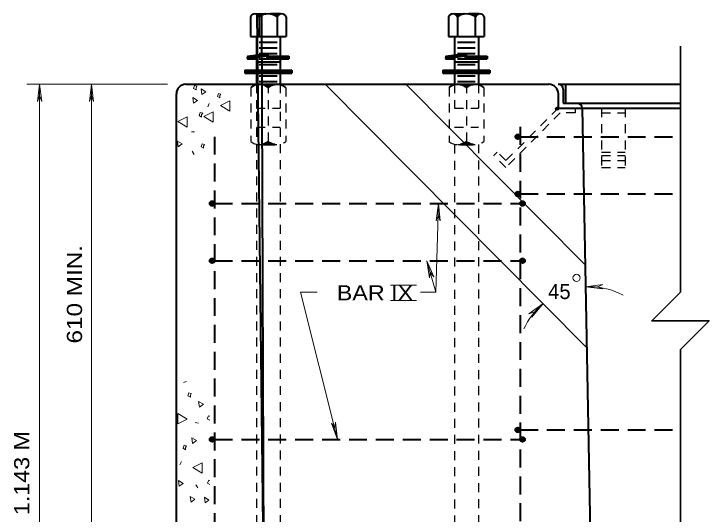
# Model space of a CAD drawing. Extents: x 312583 to 312854, y 144419 to 144597.
# Drawn here: x 312746.73 to 312781.61, y 144471.31 to 144496.43 of the extents above; entities that cross this region are included whole.
import ezdxf

# ---------------------------------------------------------------- set-up
doc = ezdxf.new("R2010")
doc.units = 0
doc.header["$LTSCALE"] = 0.3
doc.header["$PDMODE"] = 32
doc.header["$PDSIZE"] = 0.15
doc.linetypes.add('MEDIUM_DASHED', pattern=[4.5, 3, -1.5])
doc.linetypes.add('SHORT_DASHED', pattern=[2.7, 1.5, -1.2])
doc.layers.add('1', color=7, linetype='Continuous', lineweight=25)
doc.layers.add('2', color=7, linetype='Continuous', lineweight=13)

msp = doc.modelspace()

# ---------------------------------------------------------------- linework, layer by layer
at = {"layer": '1', "lineweight": 40}
for p, q in [((312758.5997, 144496.2928), (312758.5997, 144495.3038)), ((312759.0443, 144496.2928), (312759.0443, 144495.3038)), ((312759.9413, 144496.2928), (312759.9413, 144495.3038)), ((312760.3937, 144496.2928), (312760.3937, 144495.3038)), ((312768.5433, 144496.2928), (312768.5433, 144495.3038)), ((312768.988, 144496.2928), (312768.988, 144495.3038)), ((312769.885, 144496.2928), (312769.885, 144495.3038)), ((312770.3373, 144496.2928), (312770.3373, 144495.3038)), ((312758.5997, 144495.3038), (312760.3937, 144495.3038)), ((312758.8987, 144495.3038), (312758.8987, 144492.9041)), ((312759.0443, 144495.0201), (312759.9413, 144495.0201)), ((312760.0947, 144495.3038), (312760.0947, 144492.9041)), ((312768.5433, 144495.3038), (312770.3373, 144495.3038)), ((312768.8423, 144495.3038), (312768.8423, 144492.9041)), ((312768.988, 144495.0201), (312769.885, 144495.0201)), ((312770.0383, 144495.3038), (312770.0383, 144492.9041)), ((312759.0443, 144494.7364), (312759.9413, 144494.7364)), ((312768.988, 144494.7364), (312769.885, 144494.7364)), ((312758.454, 144494.3148), (312758.454, 144494.1768)), ((312759.0443, 144494.4528), (312759.9413, 144494.4528)), ((312759.4507, 144494.3148), (312760.5317, 144494.3148)), ((312760.5317, 144494.3148), (312760.5317, 144494.1768)), ((312768.3977, 144494.3148), (312768.3977, 144494.1768)), ((312768.988, 144494.4528), (312769.885, 144494.4528)), ((312769.3943, 144494.3148), (312770.4753, 144494.3148)), ((312770.4753, 144494.3148), (312770.4753, 144494.1768)), ((312758.8987, 144494.0311), (312760.0947, 144494.0311)), ((312759.0443, 144494.1768), (312759.9413, 144494.1768)), ((312759.4123, 144494.1768), (312760.5317, 144494.1768)), ((312768.8423, 144494.0311), (312770.0383, 144494.0311)), ((312768.988, 144494.1768), (312769.885, 144494.1768)), ((312769.356, 144494.1768), (312770.4753, 144494.1768)), ((312758.316, 144493.6094), (312760.6773, 144493.6094)), ((312758.316, 144493.6094), (312758.316, 144493.4638)), ((312759.0443, 144493.8931), (312759.9413, 144493.8931)), ((312760.6773, 144493.6094), (312760.6773, 144493.4638)), ((312768.2597, 144493.6094), (312770.621, 144493.6094)), ((312768.2597, 144493.6094), (312768.2597, 144493.4638)), ((312768.988, 144493.8931), (312769.885, 144493.8931)), ((312770.621, 144493.6094), (312770.621, 144493.4638)), ((312758.316, 144493.5711), (312760.6773, 144493.5711)), ((312758.316, 144493.5328), (312760.6773, 144493.5328)), ((312758.316, 144493.5021), (312760.6773, 144493.5021)), ((312758.316, 144493.4638), (312760.6773, 144493.4638)), ((312759.0443, 144493.3258), (312759.9413, 144493.3258)), ((312768.2597, 144493.5711), (312770.621, 144493.5711)), ((312768.2597, 144493.5328), (312770.621, 144493.5328)), ((312768.2597, 144493.5021), (312770.621, 144493.5021)), ((312768.2597, 144493.4638), (312770.621, 144493.4638)), ((312768.988, 144493.3258), (312769.885, 144493.3258)), ((312755.3643, 144492.9041), (312773.5727, 144492.9041)), ((312758.8987, 144492.9041), (312760.0947, 144492.9041)), ((312759.0443, 144493.0421), (312759.9413, 144493.0421)), ((312759.0597, 144492.9041), (312759.9337, 144492.9041)), ((312768.8423, 144492.9041), (312770.0383, 144492.9041)), ((312768.988, 144493.0421), (312769.885, 144493.0421)), ((312769.0033, 144492.9041), (312769.8773, 144492.9041)), ((312774.048, 144492.9041), (312780.1813, 144492.9041)), ((312774.4083, 144492.9041), (312774.4083, 144491.9458)), ((312774.2933, 144492.6588), (312774.2933, 144491.9458)), ((312754.8813, 144492.4211), (312754.8813, 144449.7791)), ((312774.048, 144492.4211), (312774.048, 144491.7004)), ((312774.2933, 144491.9458), (312780.1813, 144491.9458)), ((312774.048, 144491.7004), (312780.1813, 144491.7004)), ((312775.2517, 144491.7004), (312775.9647, 144453.6124))]:
    msp.add_line(p, q, dxfattribs=at)
at = {"layer": '1', "linetype": 'SHORT_DASHED'}
for p, q in [((312758.8987, 144492.9041), (312758.8987, 144491.6928)), ((312759.4967, 144492.9041), (312759.4967, 144489.8681)), ((312760.0947, 144492.9041), (312760.0947, 144491.6928)), ((312768.8423, 144492.9041), (312768.8423, 144491.6928)), ((312769.4403, 144492.9041), (312769.4403, 144489.8681)), ((312770.0383, 144492.9041), (312770.0383, 144491.6928)), ((312758.6227, 144492.7431), (312758.6227, 144490.0291)), ((312760.3707, 144492.7431), (312760.3707, 144490.0291)), ((312768.5663, 144492.7431), (312768.5663, 144490.0291)), ((312770.3143, 144492.7431), (312770.3143, 144490.0291)), ((312758.8987, 144491.6928), (312760.0947, 144491.6928)), ((312758.8987, 144491.5164), (312758.8987, 144458.2738)), ((312760.0947, 144491.5164), (312760.0947, 144458.2738)), ((312768.8423, 144491.6928), (312770.0383, 144491.6928)), ((312774.048, 144491.7004), (312771.4183, 144489.0708)), ((312774.8913, 144491.7004), (312774.8913, 144491.4628)), ((312776.21, 144491.7004), (312776.21, 144488.7258)), ((312777.406, 144491.7004), (312777.406, 144488.7258)), ((312774.1477, 144491.4628), (312771.4183, 144488.7258)), ((312774.8913, 144491.4628), (312774.1477, 144491.4628)), ((312776.21, 144491.4628), (312777.406, 144491.4628)), ((312758.8987, 144490.7421), (312760.0947, 144490.7421)), ((312768.8423, 144490.7421), (312770.0383, 144490.7421)), ((312759.0597, 144489.8681), (312759.9337, 144489.8681)), ((312768.8423, 144489.8681), (312768.8423, 144458.2738)), ((312769.0033, 144489.8681), (312769.8773, 144489.8681)), ((312770.0383, 144489.8834), (312770.0383, 144458.2738)), ((312770.989, 144489.4924), (312770.8203, 144489.3238)), ((312771.4183, 144489.0708), (312770.989, 144489.4924)), ((312776.21, 144489.4924), (312777.406, 144489.4924)), ((312771.4183, 144488.7258), (312770.8203, 144489.3238)), ((312776.21, 144489.3238), (312777.406, 144489.3238)), ((312776.21, 144489.0708), (312777.406, 144489.0708)), ((312776.21, 144488.7258), (312777.406, 144488.7258))]:
    msp.add_line(p, q, dxfattribs=at)
at = {"layer": '1', "lineweight": 35}
for p, q in [((312775.474, 144479.6714), (312762.3487, 144492.9041)), ((312775.3973, 144483.8344), (312766.3967, 144492.9041))]:
    msp.add_line(p, q, dxfattribs=at)
at = {"layer": '1', "lineweight": 13}
for p, q in [((312754.9043, 144491.3324), (312754.9043, 144491.8538)), ((312756.5373, 144491.9304), (312756.4607, 144491.7618)), ((312754.8813, 144491.3478), (312754.9043, 144491.3324)), ((312755.6403, 144490.5121), (312755.7937, 144490.5198)), ((312755.6787, 144489.5384), (312755.7707, 144489.3698)), ((312754.9043, 144488.9788), (312754.8813, 144488.9634)), ((312755.2417, 144477.9311), (312755.3873, 144477.9694)), ((312755.8243, 144475.9148), (312755.993, 144475.8764)), ((312755.142, 144473.9598), (312755.0653, 144473.7911)), ((312755.855, 144472.7791), (312755.9547, 144472.6334))]:
    msp.add_line(p, q, dxfattribs=at)
at = {"layer": '1', "linetype": 'MEDIUM_DASHED', "lineweight": 40}
for p, q in [((312772.1313, 144490.7574), (312772.1313, 144451.0748)), ((312756.798, 144490.2668), (312756.798, 144450.5994)), ((312772.1313, 144490.2668), (312780.1813, 144490.2668)), ((312772.1313, 144487.3918), (312780.1813, 144487.3918)), ((312756.798, 144486.9088), (312772.1313, 144486.9088)), ((312756.798, 144484.0338), (312772.1313, 144484.0338)), ((312772.1313, 144475.5468), (312780.1813, 144475.5468)), ((312756.798, 144475.0638), (312772.1313, 144475.0638))]:
    msp.add_line(p, q, dxfattribs=at)
at = {"layer": '1', "lineweight": 40}
for points in [[(312758.8757, 144496.4308), (312759.3817, 144496.4308), (312759.2973, 144496.4154), (312759.236, 144496.4001), (312759.144, 144496.3694), (312759.052, 144496.3004), (312759.0137, 144496.3618), (312758.9753, 144496.3924), (312758.8987, 144496.4308), (312759.3433, 144496.4308), (312759.213, 144496.4001), (312759.121, 144496.3618), (312759.052, 144496.3158), (312758.983, 144496.3848), (312758.9293, 144496.4231), (312759.2897, 144465.0204), (312759.167, 144496.3848), (312759.052, 144496.3234), (312758.9523, 144496.4154), (312759.2437, 144496.4154), (312759.052, 144496.3388), (312758.9753, 144496.4078), (312759.213, 144496.4154), (312759.0443, 144496.3464), (312758.9907, 144496.4001), (312759.1747, 144496.4078), (312759.052, 144496.3618), (312759.0137, 144496.3924), (312759.1287, 144496.4001), (312759.0597, 144496.3694), (312759.0367, 144496.3924), (312759.0903, 144496.3924), (312759.052, 144496.3848)], [(312760.11, 144496.4308), (312759.6117, 144496.4308), (312759.696, 144496.4154), (312759.7497, 144496.4001), (312759.8493, 144496.3694), (312759.9413, 144496.3004), (312759.972, 144496.3618), (312760.018, 144496.3924), (312760.0947, 144496.4308), (312759.65, 144496.4308), (312759.7803, 144496.4001), (312759.8647, 144496.3618), (312759.9337, 144496.3158), (312760.0103, 144496.3848), (312760.064, 144496.4231), (312759.7037, 144496.4231), (312759.8263, 144496.3848), (312759.9337, 144496.3234), (312760.0333, 144496.4154), (312759.7497, 144496.4154), (312759.9413, 144496.3388), (312760.018, 144496.4078), (312759.7803, 144496.4154), (312759.949, 144496.3464), (312760.0027, 144496.4001), (312759.811, 144496.4078), (312759.9413, 144496.3618), (312759.9797, 144496.3924), (312759.8647, 144496.4001), (312759.9337, 144496.3694), (312759.9567, 144496.3924), (312759.903, 144496.3924), (312759.9413, 144496.3848)], [(312768.8193, 144496.4308), (312769.3253, 144496.4308), (312769.241, 144496.4154), (312769.1797, 144496.4001), (312769.0877, 144496.3694), (312768.9957, 144496.3004), (312768.9573, 144496.3618), (312768.919, 144496.3924), (312768.8423, 144496.4308), (312769.287, 144496.4308), (312769.1567, 144496.4001), (312769.0647, 144496.3618), (312768.9957, 144496.3158), (312768.9267, 144496.3848), (312768.873, 144496.4231), (312769.2333, 144496.4231), (312769.1107, 144496.3848), (312768.9957, 144496.3234), (312768.896, 144496.4154), (312769.1873, 144496.4154), (312768.9957, 144496.3388), (312768.919, 144496.4078), (312769.1567, 144496.4154), (312768.988, 144496.3464), (312768.9343, 144496.4001), (312769.1183, 144496.4078), (312768.9957, 144496.3618), (312768.9573, 144496.3924), (312769.0723, 144496.4001), (312769.0033, 144496.3694), (312768.9803, 144496.3924), (312769.034, 144496.3924), (312768.9957, 144496.3848)], [(312770.0537, 144496.4308), (312769.5553, 144496.4308), (312769.6397, 144496.4154), (312769.6933, 144496.4001), (312769.793, 144496.3694), (312769.885, 144496.3004), (312769.9157, 144496.3618), (312769.9617, 144496.3924), (312770.0383, 144496.4308), (312769.5937, 144496.4308), (312769.724, 144496.4001), (312769.8083, 144496.3618), (312769.8773, 144496.3158), (312769.954, 144496.3848), (312770.0077, 144496.4231), (312769.6473, 144496.4231), (312769.77, 144496.3848), (312769.8773, 144496.3234), (312769.977, 144496.4154), (312769.6933, 144496.4154), (312769.885, 144496.3388), (312769.9617, 144496.4078), (312769.724, 144496.4154), (312769.8927, 144496.3464), (312769.9463, 144496.4001), (312769.7547, 144496.4078), (312769.885, 144496.3618), (312769.9233, 144496.3924), (312769.8083, 144496.4001), (312769.8773, 144496.3694), (312769.9003, 144496.3924), (312769.8467, 144496.3924), (312769.885, 144496.3848)], [(312758.454, 144494.3148), (312759.4967, 144494.4528), (312759.4123, 144494.1768)], [(312759.4507, 144494.3148), (312758.454, 144494.1768), (312758.8987, 144494.1768)], [(312758.8987, 144494.1768), (312758.4617, 144494.1921), (312758.477, 144494.3071), (312759.466, 144494.4374), (312759.4353, 144494.3301), (312758.891, 144494.2534), (312758.8833, 144494.1921), (312758.4847, 144494.2074), (312758.4923, 144494.2841), (312759.443, 144494.4144), (312759.42, 144494.3378), (312758.868, 144494.2534), (312758.8603, 144494.2074), (312758.5, 144494.2228), (312758.5, 144494.2611), (312759.4047, 144494.3914), (312759.4047, 144494.3684), (312758.8757, 144494.2688), (312758.8373, 144494.2534), (312758.7223, 144494.2304), (312758.523, 144494.2381), (312759.3817, 144494.3761), (312758.6533, 144494.2381)], [(312759.4353, 144494.1921), (312760.5163, 144494.1921), (312760.5163, 144494.2994), (312759.4737, 144494.2918), (312759.4353, 144494.2074), (312760.501, 144494.2074), (312760.4933, 144494.2841), (312759.4813, 144494.2764), (312759.4583, 144494.2228), (312760.478, 144494.2304), (312760.4627, 144494.2534), (312760.455, 144494.2688), (312759.489, 144494.2611), (312759.4737, 144494.2381), (312760.455, 144494.2458)], [(312768.3977, 144494.3148), (312769.4403, 144494.4528), (312769.356, 144494.1768)], [(312769.3943, 144494.3148), (312768.3977, 144494.1768), (312768.8423, 144494.1768)], [(312768.8423, 144494.1768), (312768.4053, 144494.1921), (312768.4207, 144494.3071), (312769.4097, 144494.4374), (312769.379, 144494.3301), (312768.8347, 144494.2534), (312768.827, 144494.1921), (312768.4283, 144494.2074), (312768.436, 144494.2841), (312769.3867, 144494.4144), (312769.3637, 144494.3378), (312768.8117, 144494.2534), (312768.804, 144494.2074), (312768.4437, 144494.2228), (312768.4437, 144494.2611), (312769.3483, 144494.3914), (312769.3483, 144494.3684), (312768.8193, 144494.2688), (312768.781, 144494.2534), (312768.666, 144494.2304), (312768.4667, 144494.2381), (312769.3253, 144494.3761), (312768.597, 144494.2381)], [(312769.379, 144494.1921), (312770.46, 144494.1921), (312770.46, 144494.2994), (312769.4173, 144494.2918), (312769.379, 144494.2074), (312770.4447, 144494.2074), (312770.437, 144494.2841), (312769.425, 144494.2764), (312769.402, 144494.2228), (312770.4217, 144494.2304), (312770.4063, 144494.2534), (312770.3987, 144494.2688), (312769.4327, 144494.2611), (312769.4173, 144494.2381), (312770.3987, 144494.2458)], [(312759.1747, 144492.8964), (312759.8263, 144492.8964), (312759.7497, 144492.8811), (312759.6807, 144492.8581), (312759.6117, 144492.8351), (312759.5657, 144492.8044), (312759.5043, 144492.7661), (312759.4967, 144492.7584), (312759.374, 144492.8351), (312759.2667, 144492.8734), (312759.2053, 144492.8888), (312759.7803, 144492.8964), (312759.7343, 144492.8888), (312759.6807, 144492.8734), (312759.6117, 144492.8504), (312759.535, 144492.8121), (312759.5197, 144492.7891), (312759.4967, 144492.7661), (312759.3893, 144492.8428), (312759.2667, 144492.8811), (312759.696, 144492.8888), (312759.5887, 144492.8504), (312759.4967, 144492.7891), (312759.3127, 144492.8811), (312759.65, 144492.8811), (312759.4967, 144492.7814), (312759.351, 144492.8734), (312759.6193, 144492.8734), (312759.5043, 144492.8121), (312759.4047, 144492.8581), (312759.5733, 144492.8658), (312759.4967, 144492.8351), (312759.397, 144492.8504), (312759.4583, 144492.8198), (312759.4737, 144492.8581), (312759.489, 144492.7968), (312759.5273, 144492.8428), (312759.558, 144492.8428), (312759.5887, 144492.8581)], [(312769.1183, 144492.8964), (312769.77, 144492.8964), (312769.6933, 144492.8811), (312769.6243, 144492.8581), (312769.5553, 144492.8351), (312769.5093, 144492.8044), (312769.448, 144492.7661), (312769.4403, 144492.7584), (312769.3177, 144492.8351), (312769.2103, 144492.8734), (312769.149, 144492.8888), (312769.724, 144492.8964), (312769.678, 144492.8888), (312769.6243, 144492.8734), (312769.5553, 144492.8504), (312769.4787, 144492.8121), (312769.4633, 144492.7891), (312769.4403, 144492.7661), (312769.333, 144492.8428), (312769.2103, 144492.8811), (312769.6397, 144492.8888), (312769.5323, 144492.8504), (312769.4403, 144492.7891), (312769.2563, 144492.8811), (312769.5937, 144492.8811), (312769.4403, 144492.7814), (312769.2947, 144492.8734), (312769.563, 144492.8734), (312769.448, 144492.8121), (312769.3483, 144492.8581), (312769.517, 144492.8658), (312769.4403, 144492.8351), (312769.3407, 144492.8504), (312769.402, 144492.8198), (312769.4173, 144492.8581), (312769.4327, 144492.7968), (312769.471, 144492.8428), (312769.5017, 144492.8428), (312769.5323, 144492.8581)], [(312759.1747, 144489.8758), (312759.8263, 144489.8681), (312759.7497, 144489.8834), (312759.6807, 144489.9064), (312759.6117, 144489.9371), (312759.5657, 144489.9601), (312759.5043, 144490.0061), (312759.4967, 144490.0138), (312759.374, 144489.9371), (312759.2667, 144489.8911), (312759.2053, 144489.8758), (312759.7803, 144489.8758), (312759.7343, 144489.8834), (312759.6807, 144489.8911), (312759.6117, 144489.9218), (312759.535, 144489.9601), (312759.5197, 144489.9754), (312759.4967, 144489.9984), (312759.3893, 144489.9294), (312759.2667, 144489.8834), (312759.696, 144489.8834), (312759.5887, 144489.9218), (312759.4967, 144489.9754), (312759.3127, 144489.8911), (312759.65, 144489.8834), (312759.4967, 144489.9908), (312759.351, 144489.8988), (312759.6193, 144489.8911), (312759.5043, 144489.9601), (312759.4047, 144489.9064), (312759.5733, 144489.9064), (312759.4967, 144489.9294), (312759.397, 144489.9141), (312759.4583, 144489.9524), (312759.4737, 144489.9141), (312759.489, 144489.9678), (312759.5273, 144489.9218), (312759.558, 144489.9218), (312759.5887, 144489.9141)], [(312769.1183, 144489.8758), (312769.77, 144489.8681), (312769.6933, 144489.8834), (312769.6243, 144489.9064), (312769.5553, 144489.9371), (312769.5093, 144489.9601), (312769.448, 144490.0061), (312769.4403, 144490.0138), (312769.3177, 144489.9371), (312769.2103, 144489.8911), (312769.149, 144489.8758), (312769.724, 144489.8758), (312769.678, 144489.8834), (312769.6243, 144489.8911), (312769.5553, 144489.9218), (312769.4787, 144489.9601), (312769.4633, 144489.9754), (312769.4403, 144489.9984), (312769.333, 144489.9294), (312769.2103, 144489.8834), (312769.6397, 144489.8834), (312769.5323, 144489.9218), (312769.4403, 144489.9754), (312769.2563, 144489.8911), (312769.5937, 144489.8834), (312769.4403, 144489.9908), (312769.2947, 144489.8988), (312769.563, 144489.8911), (312769.448, 144489.9601), (312769.3483, 144489.9064), (312769.517, 144489.9064), (312769.4403, 144489.9294), (312769.3407, 144489.9141), (312769.402, 144489.9524), (312769.4173, 144489.9141), (312769.4327, 144489.9678), (312769.471, 144489.9218), (312769.5017, 144489.9218), (312769.5323, 144489.9141)]]:
    msp.add_lwpolyline(points, dxfattribs=at)
at = {"layer": '1', "lineweight": 35}
msp.add_lwpolyline([(312780.1813, 144494.8208), (312780.1813, 144482.4621), (312778.74, 144481.0284), (312781.615, 144481.0284), (312780.1813, 144479.5871), (312780.1813, 144468.2021), (312778.74, 144466.7608), (312781.615, 144466.7608), (312780.1813, 144465.3271), (312780.1813, 144447.8624)], dxfattribs=at)
at = {"layer": '1', "lineweight": 13}
for points in [[(312755.8703, 144492.7278), (312755.9163, 144492.8121), (312755.8013, 144492.8428), (312755.74, 144492.6894), (312755.8703, 144492.6204)], [(312756.1617, 144492.3828), (312756.361, 144492.5284), (312756.1233, 144492.6664)], [(312755.7477, 144491.9458), (312755.947, 144492.0914), (312755.7093, 144492.2294)], [(312757.074, 144492.3291), (312757.12, 144492.4058), (312757.005, 144492.4441), (312756.9513, 144492.2908), (312757.074, 144492.2218)], [(312757.5647, 144491.5471), (312757.5647, 144492.0608), (312757.097, 144491.8308)], [(312756.7367, 144490.9951), (312756.7367, 144491.5164), (312756.269, 144491.2788)], [(312755.4257, 144490.7421), (312755.4257, 144491.2634), (312754.958, 144491.0258)], [(312756.154, 144491.3631), (312756.2077, 144491.4474), (312756.085, 144491.4781), (312756.0313, 144491.3248), (312756.154, 144491.2558)], [(312754.981, 144489.7608), (312755.1727, 144489.9064), (312754.9427, 144490.0444)], [(312756.246, 144489.7991), (312756.292, 144489.8834), (312756.177, 144489.9141), (312756.1233, 144489.7608), (312756.246, 144489.6918)], [(312755.5867, 144477.2948), (312755.6327, 144477.3791), (312755.5177, 144477.4098), (312755.4563, 144477.2564), (312755.5867, 144477.1874)], [(312756.0467, 144476.6891), (312756.2383, 144476.8348), (312756.0007, 144476.9728)], [(312754.958, 144476.3671), (312754.958, 144475.8534), (312755.4257, 144476.0834)], [(312755.7017, 144474.8644), (312755.901, 144475.0101), (312755.6633, 144475.1481)], [(312755.349, 144474.6574), (312755.395, 144474.7418), (312755.28, 144474.7724), (312755.2187, 144474.6268), (312755.349, 144474.5501)], [(312756.1847, 144473.3694), (312756.1847, 144473.8908), (312755.717, 144473.6531)], [(312755.027, 144472.7101), (312755.2187, 144472.8558), (312754.9887, 144473.0014)], [(312755.625, 144471.9204), (312755.8167, 144472.0661), (312755.579, 144472.2041)], [(312756.3303, 144471.8744), (312756.522, 144472.0201), (312756.292, 144472.1658)]]:
    msp.add_lwpolyline(points, close=True, dxfattribs=at)
for points in [[(312756.5603, 144476.2368), (312756.499, 144476.2521), (312756.4377, 144476.0988), (312756.5603, 144476.0374)], [(312756.5603, 144473.0091), (312756.5067, 144473.0244), (312756.4453, 144472.8711), (312756.5603, 144472.8098)], [(312754.8737, 144471.8514), (312754.9043, 144471.9128), (312754.8737, 144471.9204)]]:
    msp.add_lwpolyline(points, dxfattribs=at)
at = {"layer": '1', "lineweight": 40}
for centre, radius in [((312772.0144, 144490.2658), 0.1198), ((312772.0144, 144490.2658), 0.0838), ((312772.0144, 144490.2658), 0.0587), ((312772.0144, 144487.3908), 0.1198), ((312772.0144, 144487.3908), 0.0838), ((312772.0144, 144487.3908), 0.0587), ((312756.6811, 144486.9116), 0.1198), ((312756.6811, 144486.9116), 0.0838), ((312756.6811, 144486.9116), 0.0587), ((312772.254, 144486.9116), 0.1198), ((312772.254, 144486.9116), 0.0838), ((312772.254, 144486.9116), 0.0587), ((312756.6811, 144484.0366), 0.1198), ((312756.6811, 144484.0366), 0.0838), ((312756.6811, 144484.0366), 0.0587), ((312772.254, 144484.0366), 0.1198), ((312772.254, 144484.0366), 0.0838), ((312772.254, 144484.0366), 0.0587), ((312772.0144, 144475.5449), 0.1198), ((312772.0144, 144475.5449), 0.0838), ((312772.0144, 144475.5449), 0.0587), ((312756.6811, 144475.0657), 0.1198), ((312756.6811, 144475.0657), 0.0838), ((312756.6811, 144475.0657), 0.0587), ((312772.254, 144475.0657), 0.1198), ((312772.254, 144475.0657), 0.0838), ((312772.254, 144475.0657), 0.0587)]:
    msp.add_circle(centre, radius, dxfattribs=at)
for centre, radius, start, end in [((312758.8223, 144496.186), 0.2489, 25.60064, 154.39936), ((312759.4957, 144495.6513), 0.7836, 55.04559, 124.95441), ((312760.1691, 144496.186), 0.2489, 25.60064, 154.39936), ((312768.766, 144496.186), 0.2489, 25.60064, 154.39936), ((312769.4394, 144495.6513), 0.7836, 55.04559, 124.95441), ((312770.1128, 144496.186), 0.2489, 25.60064, 154.39936), ((312759.0575, 144492.2191), 0.6817, 50.00693, 129.99306), ((312759.9338, 144492.2191), 0.6817, 50.00694, 129.99307), ((312769.0012, 144492.2191), 0.6817, 50.00693, 129.99306), ((312769.8775, 144492.2191), 0.6817, 50.00694, 129.99307), ((312774.0509, 144492.6616), 0.2396, 0, 90), ((312775.0092, 144491.7033), 0.2396, 0, 90)]:
    msp.add_arc(centre, radius, start, end, dxfattribs=at)
at = {"layer": '1', "linetype": 'SHORT_DASHED'}
for centre, start, end in [((312759.0575, 144490.5485), 230.00694, 309.99307), ((312759.9338, 144490.5485), 230.00693, 309.99306), ((312769.0012, 144490.5485), 230.00694, 309.99307), ((312769.8775, 144490.5485), 230.00693, 309.99306)]:
    msp.add_arc(centre, 0.6817, start, end, dxfattribs=at)
at = {"layer": '1'}
msp.add_point((312773.979, 144491.6698), dxfattribs=at)
at = {"layer": '2'}
for p, q in [((312754.4443, 144492.9041), (312747.3757, 144492.9041)), ((312748.0197, 144492.9041), (312747.9123, 144492.0378)), ((312748.0197, 144492.9041), (312748.127, 144492.0378)), ((312748.0197, 144449.7791), (312748.0197, 144492.9041)), ((312750.6263, 144492.9041), (312750.519, 144492.0378)), ((312750.6263, 144469.9041), (312750.6263, 144492.9041)), ((312750.6263, 144492.9041), (312750.7337, 144492.0378)), ((312747.9123, 144492.0378), (312748.0197, 144492.3138)), ((312748.127, 144492.0378), (312748.0197, 144492.3138)), ((312750.519, 144492.0378), (312750.6263, 144492.3138)), ((312750.7337, 144492.0378), (312750.6263, 144492.3138)), ((312767.907, 144482.4621), (312768.045, 144486.9088)), ((312768.045, 144486.9088), (312767.9147, 144486.0501)), ((312768.045, 144486.9088), (312768.1293, 144486.0424)), ((312767.9147, 144486.0501), (312768.0297, 144486.3184)), ((312768.1293, 144486.0424), (312768.0297, 144486.3184)), ((312767.4547, 144484.0338), (312767.5927, 144483.1751)), ((312767.4547, 144484.0338), (312767.7997, 144483.2364)), ((312767.907, 144482.4621), (312767.4547, 144484.0338)), ((312767.5927, 144483.1751), (312767.6157, 144483.4664)), ((312767.7997, 144483.2364), (312767.6157, 144483.4664)), ((312765.6223, 144482.8077), (312766.9333, 144482.8077)), ((312775.4203, 144482.7304), (312776.2867, 144482.8454)), ((312776.2867, 144482.8454), (312776.0107, 144482.7304)), ((312767.1327, 144482.4621), (312767.907, 144482.4621)), ((312775.4203, 144482.7304), (312776.2867, 144482.6308)), ((312776.2867, 144482.6308), (312776.0107, 144482.7304)), ((312765.6223, 144482.0452), (312766.9333, 144482.0452)), ((312773.2813, 144481.8871), (312772.576, 144481.3734)), ((312773.2813, 144481.8871), (312772.7217, 144481.2124)), ((312772.576, 144481.3734), (312772.852, 144481.4808)), ((312772.7217, 144481.2124), (312772.852, 144481.4808)), ((312762.663, 144475.8764), (312762.8317, 144475.6388)), ((312762.9773, 144475.0638), (312762.663, 144475.8764)), ((312762.87, 144475.9301), (312762.8317, 144475.6388)), ((312762.9773, 144475.0638), (312762.87, 144475.9301))]:
    msp.add_line(p, q, dxfattribs=at)
msp.add_lwpolyline([(312761.95, 144482.4621), (312761.1143, 144482.4621), (312762.9773, 144475.0638)], dxfattribs=at)
msp.add_circle((312774.9649, 144483.1779), 0.1797, dxfattribs=at)
at = {"layer": '2', "lineweight": 40}
for centre, start, end in [((312755.3634, 144492.4221), 90, 180), ((312773.5717, 144492.4221), 0, 90)]:
    msp.add_arc(centre, 0.4792, start, end, dxfattribs=at)
at = {"layer": '2'}
for start, end in [(61.86121, 92.97681), (130.14212, 155.493)]:
    msp.add_arc((312775.6053, 144479.13), 3.6044, start, end, dxfattribs=at)

# ---------------------------------------------------------------- texts
for s, width, p in [('610 MIN.', 1.2, (312750.1515, 144479.8825)), ('1.143 M', 1.15, (312747.5048, 144471.2641))]:
    msp.add_text(s, height=0.76, rotation=90, dxfattribs=dict(at, width=width)).set_placement(p)
at = {"layer": '2', "width": 1.15}
msp.add_text('BAR IX', height=0.76, dxfattribs=at).set_placement((312762.9352, 144482.0486))
at = {"layer": '2'}
msp.add_text('45', height=0.76, dxfattribs=at).set_placement((312773.5364, 144482.1152))

doc.saveas('drawing.dxf')
